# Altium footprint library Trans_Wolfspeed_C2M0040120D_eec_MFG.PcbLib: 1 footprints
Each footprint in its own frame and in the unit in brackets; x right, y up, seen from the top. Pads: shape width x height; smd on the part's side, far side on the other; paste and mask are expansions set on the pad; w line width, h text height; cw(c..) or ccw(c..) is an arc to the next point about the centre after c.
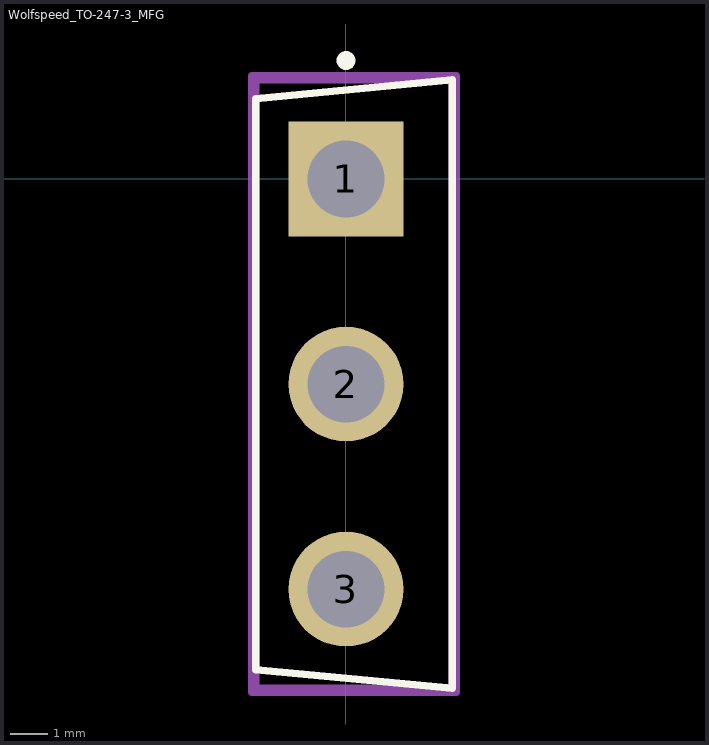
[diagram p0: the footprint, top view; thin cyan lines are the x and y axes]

## Wolfspeed_TO-247-3_MFG [mil]
pads (3):
  rect 120x120 hole 80 paste-39370.1 mask+0: 1(0,0)
  round 120 hole 80 paste-39370.1 mask+0: 2(0,-214) 3(0,-428)
Top Overlay:
  circle w9.84: c0,123.6 r4.92
  lines w7.87: -94.19,-511.83 -94.19,83.83 110.93,103.52 110.93,-531.52 -94.19,-511.83
Mechanical 10:
  lines w7.87: -98.13,-535.46 114.86,-535.46 114.86,107.46 -98.13,107.46 -98.13,-535.46
  text ".Designator" at 8.37,-214 h39.37
Mechanical 12:
  lines w7.87: -94.19,-531.52 110.93,-531.52 110.93,103.52 -94.19,103.52 -94.19,-531.52
Mechanical 15:
  lines w3.94: -19.68,0 19.68,0 ; 0,-19.68 0,19.68
  lines w7.87: -98.13,-535.46 114.86,-535.46 114.86,107.46 -98.13,107.46 -98.13,-535.46
3D body "Trans_Wolfspeed_C2M0040120D_eec.STEP": height 10, standoff 0, extent -98.13,-535.46 114.86,107.46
